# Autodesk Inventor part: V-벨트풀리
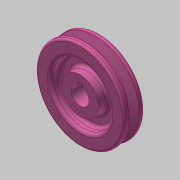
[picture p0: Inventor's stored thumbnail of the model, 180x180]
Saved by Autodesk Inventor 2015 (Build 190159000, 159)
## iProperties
Created: 2018-11
Part Number: V-벨트풀리
Material: 알루미늄 6061
Document SubType Name: Modeling
Designer: mduedu
Density: 1 g/cm^3
Appearance: 분홍색
Author: mduedu
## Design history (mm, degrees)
sketch "스케치1"
  geometry: L1 (-9.5, 0)-(9.5, 0); L2 (9.5, 0)-(9.5, 42.7); L3 (9.5, 42.7)-(-9.5, 42.7); L4 (-9.5, 42.7)-(-9.5, 0); L5 (-4.877, 42.7)-(-1.953, 33.7); L6 (-1.953, 33.7)-(1.953, 33.7); L7 (1.953, 33.7)-(4.877, 42.7); L8 (0, 0)-(0, 42.7); L9 (-9.5, 40)-(9.5, 40); 3 further points
  constraints: 18 end point, 8 point on line, 3 perpendicular, 2 midpoint, 2 parallel, 1 coincident, 1 horizontal, 1 other
  dimensions: "d0" = 85.4 diameter of L3 L1; "d2" = 19 distance of L2.end L3.end; "d3" = 80 diameter of L9 L1; "d4" = 36 deg angle of L7 L5; "d5" = 6.3 distance between parallel lines of L6 L9; "d6" = 8 distance of point (4, 40) point (-4, 40)
revolve "회전1" sketch "스케치1" stored, may be unused: angle "d7" = 90 deg
sketch "스케치2"
  geometry: L1 (-2.5, 8.124)-(2.5, 8.124); L2 (2.5, 8.124)-(2.5, 10.8); L3 (2.5, 10.8)-(-2.5, 10.8); L4 (-2.5, 10.8)-(-2.5, 8.124); A1 r 8.5 centre (0, 0) between (-2.5, 8.124) and (2.5, 8.124); 1 further point
  constraints: 8 end point, 2 parallel, 2 point on circle, 1 centre point, 1 coincident, 1 horizontal, 1 perpendicular
  dimensions: "d8" = 17 diameter of A1; "d10" = 19.3 dimension on A1 L3; "d11" = 5 distance of L2.end L3.end
extrude "돌출1" cut sketch "스케치2" stored distance "d12" = 10; taper "d13" = 0 deg
chamfer "모따기1" distance "d14" = 1; stored, may be unused: second distance "d15" = 2, angle "d16" = 45 deg
fillet "모깎기1" dims "d17" = 1, "d18" = 0.5, "d19" = 2
sketch "스케치3"
  geometry: C1 r 17.5 at (0, 0); C2 r 28.5 at (0, 0); 1 further point
  constraints: 2 centre point, 2 coincident
  dimensions: "d20" = 35 diameter of C1; "d23" = 57 diameter of C2
extrude "돌출2" cut sketch "스케치3" distance "d24" = 9.5; taper "d25" = 0 deg
fillet "모깎기2" dims "d26" = 3
node "솔리드1"
